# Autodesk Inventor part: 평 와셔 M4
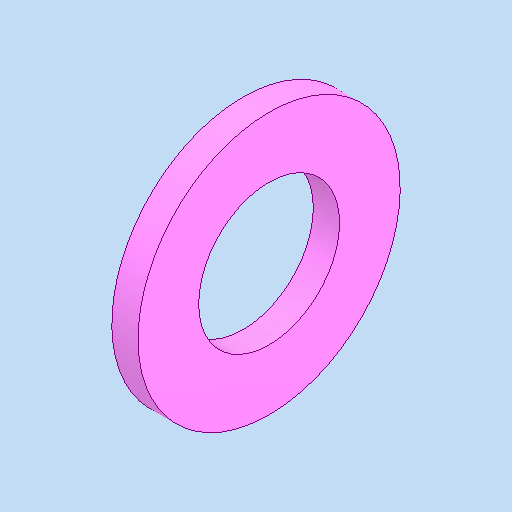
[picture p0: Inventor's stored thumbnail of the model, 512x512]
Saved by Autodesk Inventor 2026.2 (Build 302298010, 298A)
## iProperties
Created: 2026-03
Part Number: 평 와셔 M4
Material: 강철, 연강
Description: 평면 와셔
Document SubType Name: Modeling
Designer: PC-2-06
Density: 7.85 g/cm^3
Appearance: 기본값
Author: jhkim
Sending System: Autodesk Inventor 2026
Preprocessor: ST-DEVELOPER v20.1
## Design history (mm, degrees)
feature "Solid1"
node "솔리드1"
